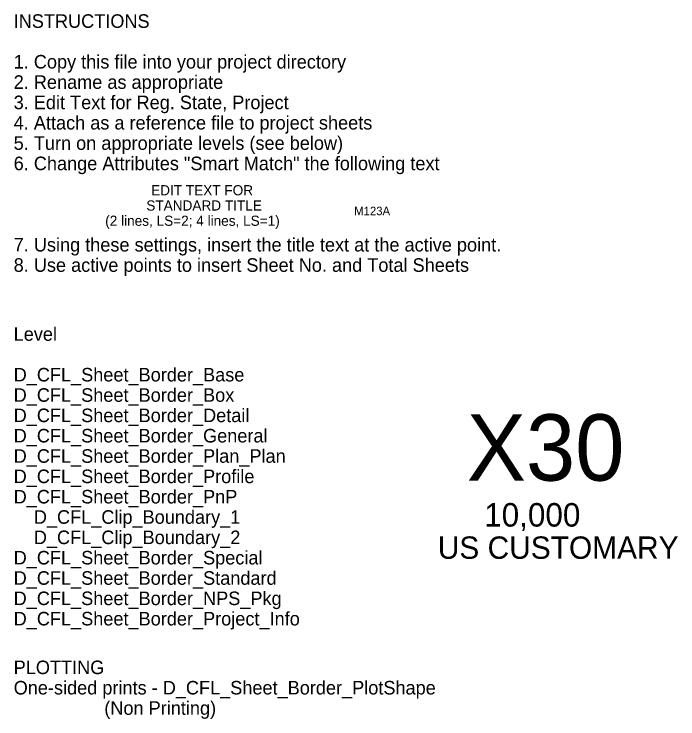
# Model space of a CAD drawing. Extents: x -87 to 2484, y -13 to 1056.
# Drawn here: x 1700 to 2484, y 224 to 1056 of the extents above; entities that cross this region are included whole.
import ezdxf

# ---------------------------------------------------------------- set-up
doc = ezdxf.new("R2010")
doc.units = 0
doc.layers.add('D_CFL_Sheet_Border_Base', color=7, linetype='Continuous')

msp = doc.modelspace()

# ---------------------------------------------------------------- texts
at = {"layer": 'D_CFL_Sheet_Border_Base'}
for s, height, p in [('INSTRUCTIONS', 16.0001, (1699.37, 1039.83)), ('INSTRUCTIONS', 16.0001, (1699.37, 1039.83)), ('1. Copy this file into your project directory', 16.0001, (1699.37, 991.83)), ('1. Copy this file into your project directory', 16.0001, (1699.37, 991.83)), ('2. Rename as appropriate', 16.0001, (1699.37, 967.83)), ('2. Rename as appropriate', 16.0001, (1699.37, 967.83)), ('3. Edit Text for Reg. State, Project', 16.0001, (1699.37, 943.83)), ('3. Edit Text for Reg. State, Project', 16.0001, (1699.37, 943.83)), ('4. Attach as a reference file to project sheets', 16.0001, (1699.37, 919.83)), ('4. Attach as a reference file to project sheets', 16.0001, (1699.37, 919.83)), ('5. Turn on appropriate levels (see below)', 16.0001, (1699.37, 895.83)), ('5. Turn on appropriate levels (see below)', 16.0001, (1699.37, 895.83)), ('6. Change Attributes "Smart Match" the following text', 16.0001, (1699.37, 871.83)), ('6. Change Attributes "Smart Match" the following text', 16.0001, (1699.37, 871.83)), ('       EDIT TEXT FOR      ', 12, (1830.43, 842.16)), ('       EDIT TEXT FOR      ', 12, (1830.43, 842.16)), ('       STANDARD TITLE     ', 12, (1824.77, 824.16)), ('       STANDARD TITLE     ', 12, (1824.77, 824.16)), ('M123A', 10, (2101.39, 818.7)), ('M123A', 10, (2101.39, 818.7)), ('(2 lines, LS=2; 4 lines, LS=1)', 12, (1807.43, 806.16)), ('(2 lines, LS=2; 4 lines, LS=1)', 12, (1807.43, 806.16)), ('7. Using these settings, insert the title text at the active point.', 16.0001, (1699.37, 775.83)), ('7. Using these settings, insert the title text at the active point.', 16.0001, (1699.37, 775.83)), ('8. Use active points to insert Sheet No. and Total Sheets', 16.0001, (1699.37, 751.83)), ('8. Use active points to insert Sheet No. and Total Sheets', 16.0001, (1699.37, 751.83)), ('Level ', 16, (1699.37, 670.41)), ('Level ', 16, (1699.37, 670.41)), ('D_CFL_Sheet_Border_Base', 16.0001, (1699.37, 622.41)), ('D_CFL_Sheet_Border_Base', 16.0001, (1699.37, 622.41)), ('D_CFL_Sheet_Border_Box', 16.0001, (1699.37, 598.41)), ('D_CFL_Sheet_Border_Box', 16.0001, (1699.37, 598.41)), ('D_CFL_Sheet_Border_Detail', 16.0001, (1699.37, 574.41)), ('D_CFL_Sheet_Border_Detail', 16.0001, (1699.37, 574.41)), ('X30', 78.275, (2234.27, 505.35)), ('X30', 78.275, (2234.27, 505.35)), ('D_CFL_Sheet_Border_General', 16.0001, (1699.37, 550.41)), ('D_CFL_Sheet_Border_General', 16.0001, (1699.37, 550.41)), ('D_CFL_Sheet_Border_Plan_Plan', 16.0001, (1699.37, 526.41)), ('D_CFL_Sheet_Border_Plan_Plan', 16.0001, (1699.37, 526.41)), ('D_CFL_Sheet_Border_Profile', 16.0001, (1699.37, 502.41)), ('D_CFL_Sheet_Border_Profile', 16.0001, (1699.37, 502.41)), ('D_CFL_Sheet_Border_PnP', 16.0001, (1699.37, 478.41)), ('D_CFL_Sheet_Border_PnP', 16.0001, (1699.37, 478.41)), ('10,000', 27.772, (2254.85, 451.09)), ('10,000', 27.772, (2254.85, 451.09)), ('    D_CFL_Clip_Boundary_1', 16.0001, (1699.37, 454.41)), ('    D_CFL_Clip_Boundary_1', 16.0001, (1699.37, 454.41)), ('    D_CFL_Clip_Boundary_2', 16.0001, (1699.37, 430.41)), ('    D_CFL_Clip_Boundary_2', 16.0001, (1699.37, 430.41)), ('US CUSTOMARY', 26.3901, (2200.04, 413.07)), ('US CUSTOMARY', 26.3901, (2200.04, 413.07)), ('D_CFL_Sheet_Border_Special', 16.0001, (1699.37, 406.41)), ('D_CFL_Sheet_Border_Special', 16.0001, (1699.37, 406.41)), ('D_CFL_Sheet_Border_Standard', 16.0001, (1699.37, 382.41)), ('D_CFL_Sheet_Border_Standard', 16.0001, (1699.37, 382.41)), ('D_CFL_Sheet_Border_NPS_Pkg', 16.0001, (1699.37, 358.41)), ('D_CFL_Sheet_Border_NPS_Pkg', 16.0001, (1699.37, 358.41)), ('D_CFL_Sheet_Border_Project_Info', 16.0001, (1699.37, 334.41)), ('D_CFL_Sheet_Border_Project_Info', 16.0001, (1699.37, 334.41)), ('PLOTTING', 16, (1699.37, 276.92)), ('PLOTTING', 16, (1699.37, 276.92)), ('One-sided prints - D_CFL_Sheet_Border_PlotShape ', 16.0001, (1699.37, 252.92)), ('One-sided prints - D_CFL_Sheet_Border_PlotShape ', 16.0001, (1699.37, 252.92)), ('                  (Non Printing)', 16.0001, (1699.37, 228.92)), ('                  (Non Printing)', 16.0001, (1699.37, 228.92))]:
    msp.add_text(s, height=height, dxfattribs=at).set_placement(p)

doc.saveas('drawing.dxf')
